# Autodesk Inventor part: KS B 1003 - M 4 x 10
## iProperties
IsCustomPart: 0
Created: 2009-02
Part Number: KS B 1003 - M 4 x 10
Material: Steel, Mild
Description: 6각머리 태핑 나사
Document SubType Name: Modeling
Standard: KS B 1003
Designer: SeoGD™ [www.esajin.kr]
Standards Organization: KS
Language: ko-KR
Size Designation: M 4 x 10
Categories: <MemberInstance><Categories><Category DisplayName="조임쇠" InternalName="e4da775c-781d-43d5-af7c-5136215cf5a6" Mnemonic="FSTN"><Category DisplayName="볼트" InternalN
Density: 1 g/cm^3
Author: SeoGD™ [www.esajin.kr]
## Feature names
1. Fillet2
